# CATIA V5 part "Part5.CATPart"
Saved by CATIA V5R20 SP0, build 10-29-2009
Part number: 3JT7.5X2X11.5
Revision: ANY
Definition: UNKNOWN
Nomenclature: 3JT7.5X2X11.5
Source: Unknown
Bounding box of the stored display mesh (mm): x -5.75 to 5.75, y -5.75 to 5.75, z -1 to 1
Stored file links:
  C:\Users\Utente\Desktop\IO LAVORO\3D X SITO CF\CUMSA\3D files PW\pw060622\pw060622_injection\Part5.CATPart
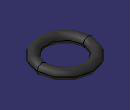
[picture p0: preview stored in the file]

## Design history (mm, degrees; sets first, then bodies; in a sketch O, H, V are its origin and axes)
Body1 "Revolución1" (main body)
  Solid1: solid without history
